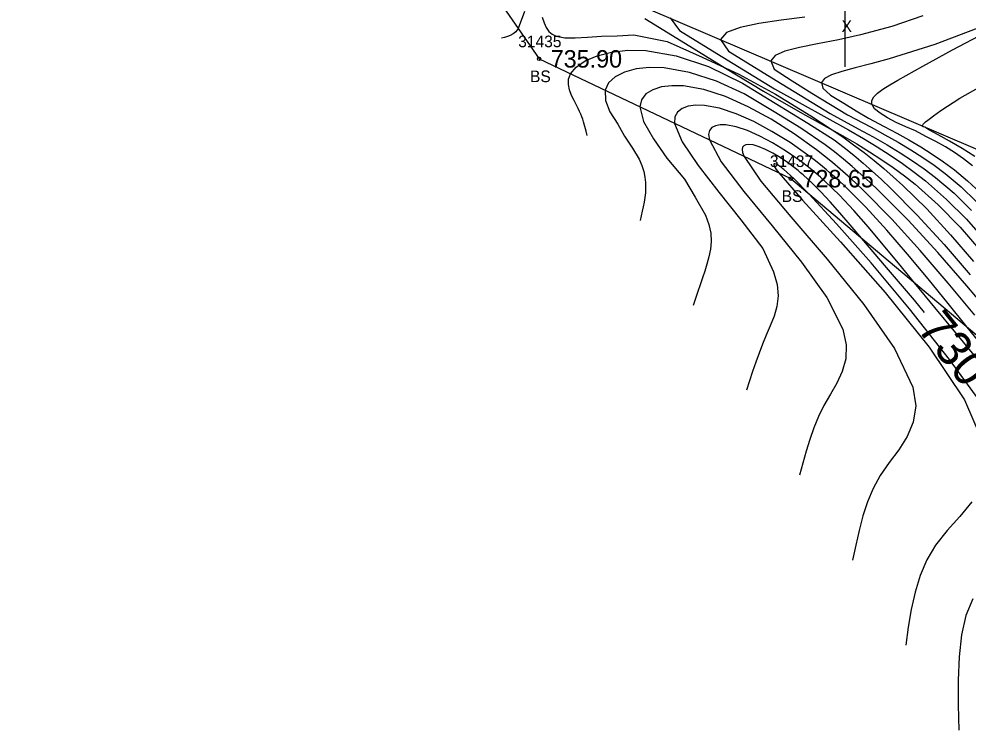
# Model space of a CAD drawing. Extents: x 1376587 to 1378239, y 1000335 to 1003031.
# Drawn here: x 1376913.1 to 1376994.7, y 1002073.9 to 1002135.1 of the extents above; entities that cross this region are included whole.
import ezdxf

# ---------------------------------------------------------------- set-up
doc = ezdxf.new("R2010")
doc.units = 0
for name, color, linetype in [('RD_DTM_BkLn2', 7, 'Continuous'), ('RD_DTM_BkLn_txCode', 7, 'Continuous'), ('RD_DTM_Major1', 7, 'Continuous'), ('RD_DTM_Major1_Lbl', 7, 'Continuous'), ('RD_DTM_Minor1', 7, 'Continuous'), ('RD_EX_Misc', 7, 'Continuous'), ('RD_EX_Misc_txCode', 7, 'Continuous'), ('RD_EX_TX_Misc_ELEV', 7, 'Continuous'), ('RD_SMD_Locator', 7, 'Continuous')]:
    doc.layers.add(name, color=color, linetype=linetype)

msp = doc.modelspace()

# ---------------------------------------------------------------- linework, layer by layer
at = {"layer": 'RD_DTM_BkLn2'}
for points in [[(1376913.098, 1002240.931), (1376931.705, 1002209.803), (1376942.212, 1002154.179), (1376957.8, 1002131.633), (1376979.434, 1002121.337), (1377012.712, 1002093.32), (1377057.146, 1002084.693), (1377074.255, 1002080.067)], [(1376936.615, 1002231.523), (1376941.43, 1002209.491), (1376964.025, 1002137.317), (1376998.233, 1002122.674), (1377013.665, 1002101.927), (1377028.204, 1002101.481)]]:
    msp.add_lwpolyline(points, dxfattribs=at)
at = {"layer": 'RD_DTM_Major1'}
for points in [[(1376956.543, 1002135.711), (1376956, 1002134.236), (1376955.792, 1002133.969), (1376955.566, 1002133.774), (1376955.326, 1002133.636), (1376955.076, 1002133.542), (1376954.818, 1002133.476), (1376954.557, 1002133.425)], [(1376990.772, 1002135.333), (1376988.128, 1002134.417), (1376985.436, 1002133.69), (1376983.522, 1002133.277), (1376981.741, 1002132.931), (1376980.182, 1002132.614), (1376978.933, 1002132.287), (1376978.085, 1002131.913), (1376977.724, 1002131.453), (1376978.015, 1002130.743), (1376979.555, 1002129.732), (1376981.248, 1002128.696), (1376982.856, 1002127.71), (1376984.316, 1002126.82), (1376986.335, 1002125.754), (1376987.526, 1002125.108), (1376988.66, 1002124.468), (1376989.741, 1002123.823), (1376990.774, 1002123.165), (1376991.763, 1002122.484), (1376992.711, 1002121.77), (1376994.068, 1002120.621), (1376995.355, 1002119.377)], [(1376961.922, 1002125.042), (1376961.835, 1002125.431), (1376961.788, 1002125.626), (1376961.739, 1002125.823), (1376961.684, 1002126.021), (1376961.624, 1002126.22), (1376961.55, 1002126.44), (1376961.468, 1002126.663), (1376961.377, 1002126.89), (1376961.276, 1002127.123), (1376961.165, 1002127.363), (1376961.044, 1002127.61), (1376960.819, 1002128.044), (1376960.599, 1002128.496), (1376960.42, 1002128.959), (1376960.319, 1002129.426), (1376960.332, 1002129.892), (1376960.495, 1002130.35), (1376960.987, 1002130.932), (1376961.767, 1002131.457), (1376962.796, 1002131.893), (1376964.032, 1002132.209), (1376965.435, 1002132.372), (1376966.963, 1002132.352), (1376969.59, 1002131.895), (1376972.354, 1002130.98), (1376975.278, 1002129.553), (1376980.9, 1002126.111), (1376983.149, 1002124.666), (1376984.009, 1002124.007), (1376984.839, 1002123.344), (1376985.647, 1002122.67), (1376986.441, 1002121.98), (1376987.227, 1002121.267), (1376988.013, 1002120.524), (1376990.304, 1002118.203), (1376992.602, 1002115.687), (1376994.853, 1002113.085)], [(1376990.935, 1002109.848), (1376990.063, 1002110.894), (1376987.665, 1002113.713), (1376985.529, 1002116.205), (1376984.541, 1002117.362), (1376983.641, 1002118.405), (1376982.81, 1002119.347), (1376982.024, 1002120.196), (1376981.263, 1002120.964), (1376980.504, 1002121.662), (1376980.282, 1002121.852), (1376980.059, 1002122.037), (1376979.833, 1002122.217), (1376979.606, 1002122.392), (1376979.377, 1002122.563), (1376979.145, 1002122.729), (1376978.51, 1002123.153), (1376977.878, 1002123.53), (1376977.268, 1002123.846), (1376976.702, 1002124.086), (1376976.197, 1002124.236), (1376975.775, 1002124.282), (1376975.563, 1002124.252), (1376975.4, 1002124.171), (1376975.294, 1002124.035), (1376975.257, 1002123.839), (1376975.295, 1002123.578), (1376975.419, 1002123.248), (1376976.87, 1002121.127), (1376979.434, 1002118.065), (1376982.567, 1002114.412), (1376985.723, 1002110.52), (1376988.358, 1002106.741), (1376989.926, 1002103.427), (1376990.168, 1002101.804), (1376989.965, 1002100.406), (1376989.438, 1002099.17), (1376988.707, 1002098.034), (1376987.893, 1002096.936), (1376987.115, 1002095.813), (1376986.516, 1002094.714), (1376986.028, 1002093.554), (1376985.63, 1002092.345), (1376985.298, 1002091.1), (1376985.011, 1002089.83), (1376984.746, 1002088.548)]]:
    msp.add_lwpolyline(points, dxfattribs=at)
at = {"layer": 'RD_DTM_Minor1'}
for points in [[(1376958.074, 1002135.224), (1376958.223, 1002134.732), (1376958.414, 1002134.324), (1376958.65, 1002133.996), (1376958.938, 1002133.746), (1376959.282, 1002133.571), (1376960.006, 1002133.431), (1376960.899, 1002133.433), (1376961.952, 1002133.508), (1376963.157, 1002133.589), (1376964.504, 1002133.606), (1376965.949, 1002133.696), (1376968.814, 1002133.112), (1376971.813, 1002131.78), (1376974.964, 1002130.329), (1376978.121, 1002128.612), (1376981.16, 1002126.75), (1376983.895, 1002124.928), (1376984.832, 1002124.253), (1376985.727, 1002123.581), (1376986.588, 1002122.904), (1376987.425, 1002122.214), (1376988.246, 1002121.503), (1376989.059, 1002120.762), (1376991.119, 1002118.731), (1376993.156, 1002116.523), (1376995.137, 1002114.205)], [(1376966.888, 1002135.091), (1376970.398, 1002132.942), (1376973.836, 1002130.836), (1376977.086, 1002128.845), (1376980.431, 1002126.94), (1376983.92, 1002125.011), (1376985.103, 1002124.32), (1376986.211, 1002123.643), (1376987.255, 1002122.968), (1376988.246, 1002122.285), (1376989.196, 1002121.583), (1376990.116, 1002120.851), (1376992.101, 1002119.081), (1376993.986, 1002117.155), (1376995.769, 1002115.119)], [(1376969.054, 1002135.164), (1376969.865, 1002134.077), (1376972.697, 1002132.334), (1376978.024, 1002129.071), (1376984.391, 1002125.528), (1376985.669, 1002124.786), (1376986.863, 1002124.064), (1376987.984, 1002123.351), (1376989.042, 1002122.634), (1376990.048, 1002121.904), (1376991.013, 1002121.148), (1376992.825, 1002119.56), (1376994.526, 1002117.854), (1376996.125, 1002116.056)], [(1376980.627, 1002135.206), (1376978.615, 1002134.952), (1376976.701, 1002134.677), (1376975.069, 1002134.339), (1376973.904, 1002133.897), (1376973.389, 1002133.309), (1376974.074, 1002132.29), (1376978.682, 1002129.468), (1376982.815, 1002126.936), (1376985.238, 1002125.622), (1376986.51, 1002124.927), (1376987.705, 1002124.245), (1376988.831, 1002123.567), (1376989.896, 1002122.881), (1376990.91, 1002122.176), (1376991.88, 1002121.442), (1376993.474, 1002120.082), (1376994.974, 1002118.615)], [(1376996.113, 1002134.49), (1376991.804, 1002132.862), (1376987.88, 1002131.635), (1376986.322, 1002131.215), (1376984.955, 1002130.862), (1376983.812, 1002130.548), (1376982.926, 1002130.25), (1376982.33, 1002129.942), (1376982.059, 1002129.597), (1376982.187, 1002129.105), (1376982.857, 1002128.51), (1376983.982, 1002127.82), (1376985.063, 1002127.158), (1376986.102, 1002126.53), (1376987.468, 1002125.811), (1376988.535, 1002125.24), (1376989.58, 1002124.662), (1376990.602, 1002124.067), (1376991.596, 1002123.447), (1376992.56, 1002122.796), (1376993.492, 1002122.104), (1376994.633, 1002121.152), (1376995.729, 1002120.116)], [(1376990.15, 1002125.441), (1376989.322, 1002125.796), (1376988.503, 1002126.172), (1376987.747, 1002126.561), (1376987.108, 1002126.957), (1376986.639, 1002127.353), (1376986.394, 1002127.742), (1376986.391, 1002128.054), (1376986.56, 1002128.367), (1376986.885, 1002128.688), (1376987.348, 1002129.027), (1376987.935, 1002129.394), (1376988.629, 1002129.797), (1376990.771, 1002131.004), (1376993.336, 1002132.406), (1376996.171, 1002133.906)], [(1376996.893, 1002109.366), (1376994.576, 1002112.124), (1376992.086, 1002114.978), (1376989.518, 1002117.768), (1376986.97, 1002120.333), (1376986.213, 1002121.045), (1376985.461, 1002121.726), (1376984.709, 1002122.382), (1376983.95, 1002123.017), (1376983.18, 1002123.635), (1376982.392, 1002124.243), (1376980.29, 1002125.684), (1376978.014, 1002127.078), (1376975.421, 1002128.642), (1376973.04, 1002129.711), (1376970.73, 1002130.473), (1376968.55, 1002130.863), (1376967.288, 1002130.893), (1376966.139, 1002130.766), (1376965.144, 1002130.494), (1376964.343, 1002130.089), (1376963.775, 1002129.563), (1376963.48, 1002128.93), (1376963.511, 1002128.055), (1376963.874, 1002127.083), (1376964.561, 1002126.017), (1376965.144, 1002125.003), (1376965.827, 1002123.972), (1376966.39, 1002122.999), (1376966.628, 1002122.464), (1376966.794, 1002121.958), (1376966.898, 1002121.475), (1376966.949, 1002121.011), (1376966.958, 1002120.562), (1376966.934, 1002120.121), (1376966.89, 1002119.72), (1376966.829, 1002119.321), (1376966.755, 1002118.924), (1376966.672, 1002118.53), (1376966.581, 1002118.136), (1376966.487, 1002117.743)], [(1376995.245, 1002109.608), (1376992.966, 1002112.365), (1376990.566, 1002115.159), (1376988.122, 1002117.85), (1376985.712, 1002120.302), (1376985.033, 1002120.947), (1376984.359, 1002121.564), (1376983.687, 1002122.156), (1376983.013, 1002122.726), (1376982.333, 1002123.277), (1376981.643, 1002123.813), (1376979.719, 1002125.195), (1376977.745, 1002126.444), (1376975.759, 1002127.525), (1376973.813, 1002128.389), (1376971.949, 1002128.997), (1376970.213, 1002129.304), (1376969.219, 1002129.328), (1376968.326, 1002129.221), (1376967.57, 1002128.984), (1376966.985, 1002128.618), (1376966.605, 1002128.126), (1376966.465, 1002127.509), (1376966.782, 1002126.251), (1376967.622, 1002124.756), (1376968.789, 1002123.109), (1376970.301, 1002121.297), (1376971.226, 1002119.751), (1376972.1, 1002118.214), (1376972.403, 1002117.396), (1376972.555, 1002116.641), (1376972.585, 1002115.935), (1376972.519, 1002115.267), (1376972.385, 1002114.621), (1376972.211, 1002113.986), (1376972.034, 1002113.4), (1376971.849, 1002112.811), (1376971.656, 1002112.221), (1376971.458, 1002111.63), (1376971.256, 1002111.037), (1376971.052, 1002110.444)], [(1376990.954, 1002125.749), (1376990.816, 1002125.802), (1376990.772, 1002125.822), (1376990.745, 1002125.841), (1376990.731, 1002125.862), (1376990.729, 1002125.886), (1376990.736, 1002125.91), (1376990.751, 1002125.938), (1376990.773, 1002125.971), (1376990.802, 1002126.007), (1376990.839, 1002126.047), (1376990.882, 1002126.092), (1376991.023, 1002126.221), (1376991.207, 1002126.373), (1376991.432, 1002126.548), (1376991.697, 1002126.745), (1376992.002, 1002126.962), (1376992.343, 1002127.198), (1376993.972, 1002128.25), (1376995.991, 1002129.412)], [(1376995.86, 1002107.014), (1376994.593, 1002108.574), (1376992.947, 1002110.618), (1376991.237, 1002112.729), (1376989.478, 1002114.849), (1376987.687, 1002116.922), (1376985.879, 1002118.889), (1376984.07, 1002120.692), (1376983.549, 1002121.175), (1376983.027, 1002121.641), (1376982.502, 1002122.091), (1376981.973, 1002122.528), (1376981.437, 1002122.952), (1376980.892, 1002123.366), (1376979.373, 1002124.434), (1376977.816, 1002125.403), (1376976.262, 1002126.239), (1376974.749, 1002126.911), (1376973.316, 1002127.385), (1376972.003, 1002127.63), (1376971.266, 1002127.652), (1376970.618, 1002127.569), (1376970.085, 1002127.375), (1376969.695, 1002127.066), (1376969.474, 1002126.639), (1376969.45, 1002126.089), (1376970.096, 1002124.497), (1376971.467, 1002122.477), (1376973.251, 1002120.189), (1376975.134, 1002117.795), (1376977.023, 1002115.339), (1376977.948, 1002113.343), (1376978.27, 1002112.25), (1376978.35, 1002111.264), (1376978.242, 1002110.361), (1376977.999, 1002109.514), (1376977.674, 1002108.697), (1376977.319, 1002107.885), (1376977.004, 1002107.123), (1376976.707, 1002106.345), (1376976.422, 1002105.556), (1376976.148, 1002104.757), (1376975.881, 1002103.953), (1376975.617, 1002103.145)], [(1376995.456, 1002105.866), (1376993.632, 1002108.082), (1376991.817, 1002110.268), (1376990.061, 1002112.39), (1376988.69, 1002114.064), (1376987.377, 1002115.662), (1376986.103, 1002117.176), (1376984.852, 1002118.598), (1376983.606, 1002119.921), (1376982.347, 1002121.136), (1376981.978, 1002121.466), (1376981.606, 1002121.787), (1376981.23, 1002122.099), (1376980.849, 1002122.403), (1376980.463, 1002122.7), (1376980.071, 1002122.99), (1376978.978, 1002123.738), (1376977.866, 1002124.416), (1376976.766, 1002125), (1376975.709, 1002125.467), (1376974.727, 1002125.791), (1376973.851, 1002125.951), (1376973.375, 1002125.956), (1376972.971, 1002125.882), (1376972.656, 1002125.722), (1376972.45, 1002125.47), (1376972.37, 1002125.121), (1376972.435, 1002124.668), (1376973.453, 1002122.789), (1376975.399, 1002120.245), (1376977.843, 1002117.286), (1376980.36, 1002114.16), (1376982.52, 1002111.118), (1376983.895, 1002108.409), (1376984.195, 1002107.048), (1376984.154, 1002105.849), (1376983.857, 1002104.77), (1376983.389, 1002103.768), (1376982.834, 1002102.802), (1376982.277, 1002101.829), (1376981.821, 1002100.896), (1376981.423, 1002099.928), (1376981.072, 1002098.932), (1376980.756, 1002097.915), (1376980.463, 1002096.884), (1376980.181, 1002095.847)], [(1376995.039, 1002122.447), (1376994.281, 1002123.048), (1376993.513, 1002123.581), (1376992.725, 1002124.066), (1376991.909, 1002124.523), (1376991.053, 1002124.975), (1376990.15, 1002125.441)], [(1376995.243, 1002123.247), (1376994.159, 1002123.935), (1376993.073, 1002124.562), (1376992.1, 1002125.095), (1376991.355, 1002125.502), (1376990.954, 1002125.749)], [(1376996.4, 1002101.228), (1376993.064, 1002105.798), (1376989.632, 1002110.153), (1376986.329, 1002114.101), (1376983.376, 1002117.453), (1376980.998, 1002120.021), (1376980.539, 1002120.496), (1376980.124, 1002120.919), (1376979.748, 1002121.291), (1376979.41, 1002121.614), (1376979.106, 1002121.892), (1376978.835, 1002122.125), (1376978.763, 1002122.185), (1376978.692, 1002122.241), (1376978.625, 1002122.293), (1376978.56, 1002122.343), (1376978.497, 1002122.388), (1376978.438, 1002122.43), (1376978.29, 1002122.525), (1376978.166, 1002122.591), (1376978.069, 1002122.625), (1376978.003, 1002122.625), (1376977.971, 1002122.588), (1376977.976, 1002122.512), (1376978, 1002122.444), (1376978.041, 1002122.358), (1376978.101, 1002122.255), (1376978.181, 1002122.132), (1376978.281, 1002121.99), (1376978.404, 1002121.827), (1376980.436, 1002119.497), (1376983.698, 1002115.917), (1376987.54, 1002111.552), (1376991.314, 1002106.868), (1376994.37, 1002102.329), (1376996.059, 1002098.402)], [(1376994.995, 1002093.562), (1376993.967, 1002092.308), (1376992.869, 1002091.094), (1376991.857, 1002089.833), (1376991.113, 1002088.572), (1376990.544, 1002087.218), (1376990.113, 1002085.79), (1376989.788, 1002084.307), (1376989.532, 1002082.787), (1376989.311, 1002081.249)], [(1376995.087, 1002085.236), (1376994.491, 1002083.802), (1376994.11, 1002082.123), (1376993.901, 1002080.251), (1376993.821, 1002078.232), (1376993.827, 1002076.115), (1376993.876, 1002073.95)]]:
    msp.add_lwpolyline(points, dxfattribs=at)
at = {"layer": 'RD_EX_Misc'}
msp.add_line((1376984.112, 1002130.947), (1376984.112, 1002140.947), dxfattribs=at)
at = {"layer": 'RD_SMD_Locator'}
for centre in [(1376957.8, 1002131.633), (1376979.434, 1002121.337)]:
    msp.add_circle(centre, 0.15, dxfattribs=at)

# ---------------------------------------------------------------- texts
at = {"layer": 'RD_DTM_BkLn_txCode'}
for s, p in [('31435', (1376956.005, 1002132.633)), ('BS', (1376957.02, 1002129.633)), ('31437', (1376977.639, 1002122.337)), ('BS', (1376978.654, 1002119.337))]:
    msp.add_text(s, height=1, dxfattribs=at).set_placement(p)
at = {"layer": 'RD_DTM_Major1_Lbl'}
msp.add_text('730', height=3, rotation=308.72982, dxfattribs=at).set_placement((1376990.211, 1002108.436))
at = {"layer": 'RD_EX_Misc_txCode'}
msp.add_text('X', height=1, dxfattribs=at).set_placement((1376983.797, 1002133.947))
at = {"layer": 'RD_EX_TX_Misc_ELEV'}
for s, p in [('735.90', (1376958.8, 1002130.883)), ('728.65', (1376980.434, 1002120.587))]:
    msp.add_text(s, height=1.5, dxfattribs=at).set_placement(p)

doc.saveas('drawing.dxf')
